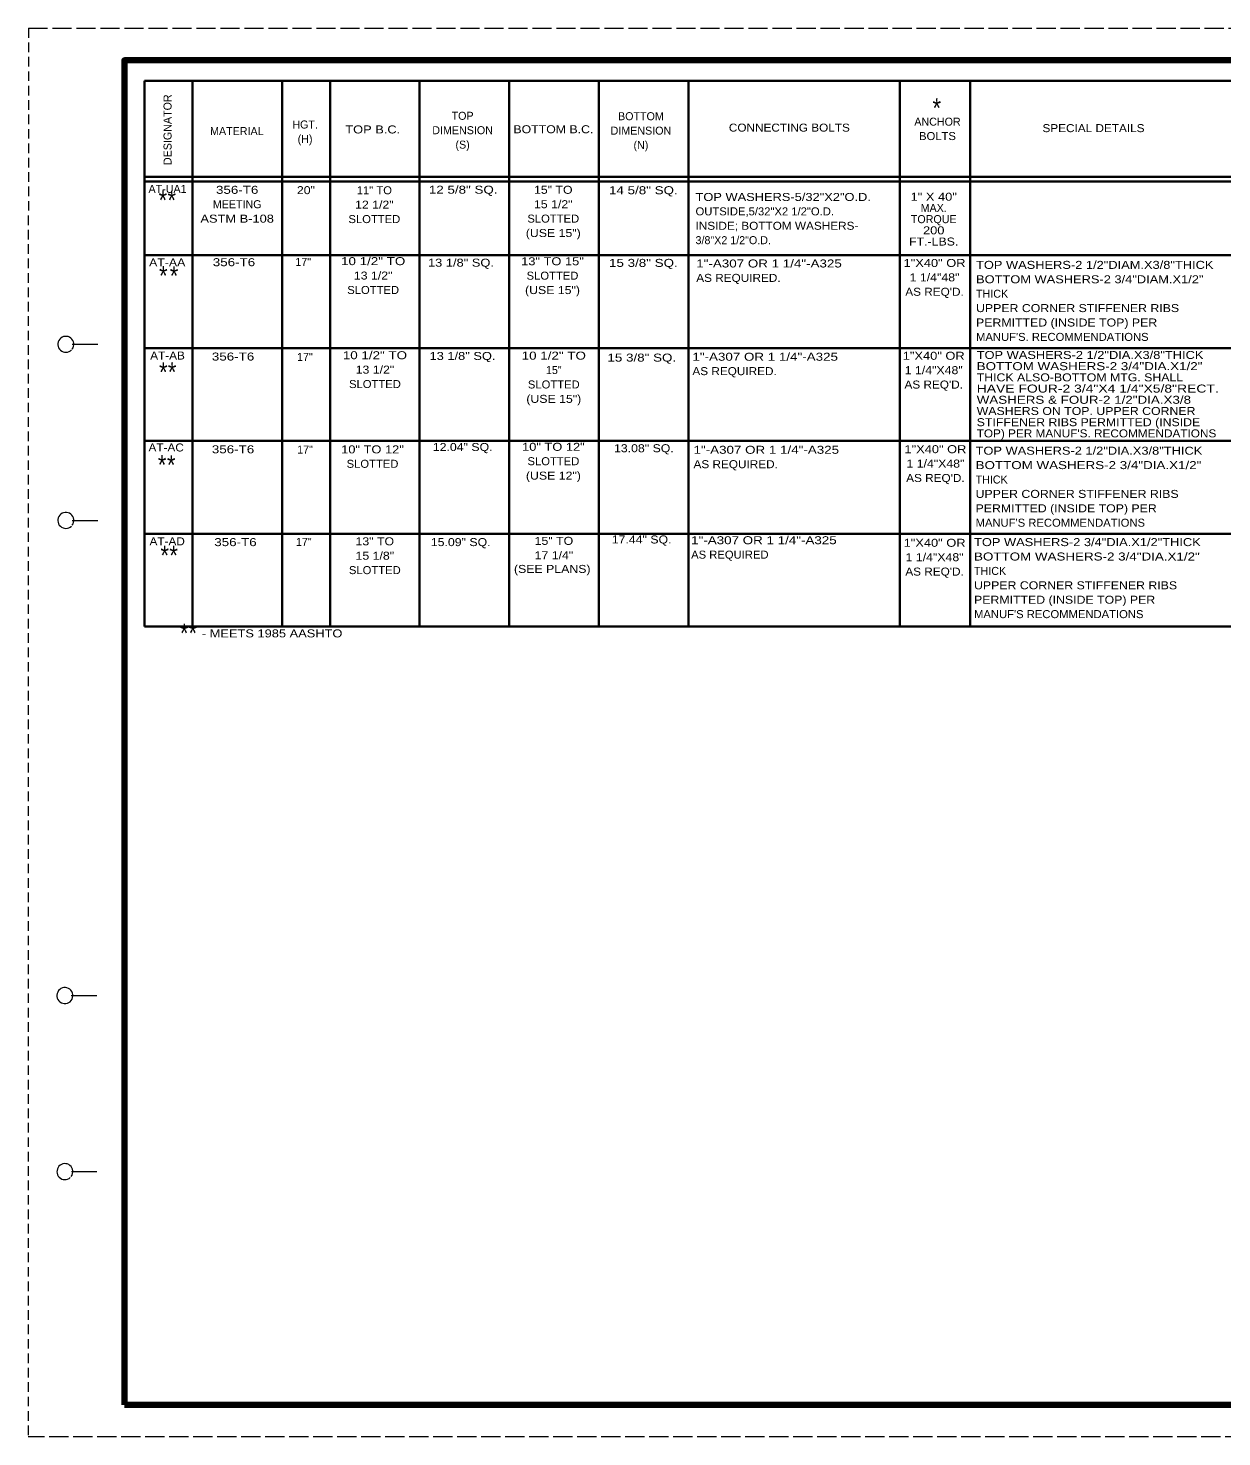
# Model space of a CAD drawing. Extents: x -993 to -313, y 154 to 594.
# Drawn here: x -993.4 to -620.4, y 154.4 to 594.4 of the extents above; entities that cross this region are included whole.
import ezdxf
from ezdxf.enums import TextEntityAlignment as Align

# ---------------------------------------------------------------- set-up
doc = ezdxf.new("R2010")
doc.units = 0
doc.linetypes.add('LONG_DASHED', pattern=[7.5, 6, -1.5])
doc.linetypes.add('MEDIUM_DASHED', pattern=[4.5, 3, -1.5])
doc.layers.add('1', color=7, linetype='Continuous', lineweight=25)
doc.layers.add('61', color=7, linetype='Continuous', lineweight=35)

msp = doc.modelspace()

# ---------------------------------------------------------------- linework, layer by layer
at = {"layer": '1', "linetype": 'MEDIUM_DASHED', "lineweight": 13}
msp.add_line((-993.343, 594.434), (-993.403, 154.394), dxfattribs=at)
at = {"layer": '1', "lineweight": 35}
for p, q in [((-957.085, 578.012), (-957.085, 407.512)), ((-520.085, 578.012), (-957.085, 578.012)), ((-942.085, 578.012), (-942.085, 407.512)), ((-914.085, 578.012), (-914.085, 407.512)), ((-899.085, 578.012), (-899.085, 407.512)), ((-871.085, 578.012), (-871.085, 407.512)), ((-843.085, 578.012), (-843.085, 407.512)), ((-815.085, 578.012), (-815.085, 407.512)), ((-787.085, 578.012), (-787.085, 407.512)), ((-721.085, 578.012), (-721.085, 407.512)), ((-699.085, 578.012), (-699.085, 407.512)), ((-520.085, 548.012), (-957.085, 548.012)), ((-520.085, 546.512), (-957.085, 546.512)), ((-520.085, 523.512), (-957.085, 523.512)), ((-520.085, 494.512), (-957.085, 494.512)), ((-520.085, 465.512), (-957.085, 465.512)), ((-520.085, 436.512), (-957.085, 436.512)), ((-520.085, 407.512), (-957.085, 407.512))]:
    msp.add_line(p, q, dxfattribs=at)
at = {"layer": '61', "linetype": 'LONG_DASHED', "lineweight": 13}
for p, q in [((-993.343, 594.434), (-313.323, 594.434)), ((-313.343, 154.414), (-993.403, 154.394))]:
    msp.add_line(p, q, dxfattribs=at)
at = {"layer": '61', "lineweight": 13}
for p, q in [((-979.623, 495.674), (-971.643, 495.694)), ((-979.643, 440.674), (-971.643, 440.674)), ((-979.923, 292.254), (-971.923, 292.254)), ((-979.903, 237.234), (-971.923, 237.234))]:
    msp.add_line(p, q, dxfattribs=at)
at = {"layer": '61', "lineweight": 158}
msp.add_line((-324.283, 164.394), (-963.343, 164.414), dxfattribs=at)
msp.add_lwpolyline([(-324.303, 584.434), (-963.343, 584.434), (-963.343, 164.414)], dxfattribs=at)
at = {"layer": '61', "lineweight": 13}
for centre, start, end in [((-981.645, 495.676), 323.13009, 316.23216), ((-981.645, 440.676), 323.13009, 315.37577), ((-981.925, 292.236), 322.67175, 321.71615), ((-981.925, 237.236), 323.13009, 312.31439)]:
    msp.add_arc(centre, 2.5, start, end, dxfattribs=at)

# ---------------------------------------------------------------- texts
at = {"layer": '1'}
msp.add_text('DESIGNATOR', height=2.5, rotation=90, dxfattribs=at).set_placement((-948.601, 551.663))
for s, height, width, p in [('*', 6, 0.85, (-710.831, 566.509)), ('*', 6, 0.85, (-952.633, 537.732)), ('*', 6, 0.85, (-949.862, 537.703)), ('TOP WASHERS-5/32"X2"O.D.', 2.5, 1.2, (-784.879, 540.456)), ('OUTSIDE,5/32"X2 1/2"O.D.', 2.5, 1.05, (-784.879, 535.956)), ('INSIDE; BOTTOM WASHERS-', 2.5, 1.1, (-784.879, 531.456)), ('*', 6, 0.85, (-952.497, 514.11)), ('*', 6, 0.85, (-949.144, 514.065)), ('1"-A307 OR 1 1/4"-A325', 2.5, 1.25, (-784.654, 519.677)), ('TOP WASHERS-2 1/2"DIAM.X3/8"THICK', 2.5, 1.2, (-697.231, 519.241)), ('AS REQUIRED.', 2.5, 1.1, (-784.654, 515.177)), ('BOTTOM WASHERS-2 3/4"DIAM.X1/2"', 2.5, 1.2, (-697.231, 514.741)), ('UPPER CORNER STIFFENER RIBS', 2.5, 1.15, (-697.231, 505.741)), ('PERMITTED (INSIDE TOP) PER', 2.5, 1.15, (-697.231, 501.241)), ("MANUF'S. RECOMMENDATIONS", 2.5, 1.05, (-697.231, 496.741)), ('AT-AB', 2.5, 1.1, (-955.271, 490.923)), ('1"-A307 OR 1 1/4"-A325', 2.5, 1.25, (-785.859, 490.544)), ('TOP WASHERS-2 1/2"DIA.X3/8"THICK', 2.5, 1.2, (-697.03, 491.101)), ('*', 6, 0.85, (-952.495, 483.998)), ('*', 6, 0.85, (-949.754, 484.021)), ('AS REQUIRED.', 2.5, 1.1, (-785.859, 486.044)), ('BOTTOM WASHERS-2 3/4"DIA.X1/2"', 2.5, 1.25, (-697.03, 487.601)), ('THICK ALSO-BOTTOM MTG. SHALL', 2.5, 1.15, (-697.03, 484.101)), ('WASHERS & FOUR-2 1/2"DIA.X3/8', 2.5, 1.25, (-697.03, 477.101)), ('HAVE FOUR-2 3/4"X4 1/4"X5/8"RECT.', 2.5, 1.3, (-697.03, 480.601)), ('WASHERS ON TOP. UPPER CORNER', 2.5, 1.15, (-697.03, 473.601)), ('STIFFENER RIBS PERMITTED (INSIDE', 2.5, 1.15, (-697.03, 470.101)), ("TOP) PER MANUF'S. RECOMMENDATIONS", 2.5, 1.1, (-697.03, 466.601)), ('1"-A307 OR 1 1/4"-A325', 2.5, 1.25, (-785.51, 461.479)), ('TOP WASHERS-2 1/2"DIA.X3/8"THICK', 2.5, 1.2, (-697.373, 461.195)), ('*', 6, 0.85, (-952.891, 455.051)), ('*', 6, 0.85, (-950.036, 455.006)), ('AS REQUIRED.', 2.5, 1.1, (-785.51, 456.979)), ('BOTTOM WASHERS-2 3/4"DIA.X1/2"', 2.5, 1.25, (-697.373, 456.695)), ('UPPER CORNER STIFFENER RIBS', 2.5, 1.15, (-697.373, 447.695)), ('PERMITTED (INSIDE TOP) PER', 2.5, 1.15, (-697.373, 443.195)), ("MANUF'S RECOMMENDATIONS", 2.5, 1.05, (-697.373, 438.695)), ('1"-A307 OR 1 1/4"-A325', 2.5, 1.25, (-786.256, 433.228)), ('*', 6, 0.85, (-952.067, 426.767)), ('*', 6, 0.85, (-949.28, 426.744)), ('AS REQUIRED', 2.5, 1.05, (-786.256, 428.728)), ('TOP WASHERS-2 3/4"DIA.X1/2"THICK', 2.5, 1.2, (-697.861, 432.641)), ('BOTTOM WASHERS-2 3/4"DIA.X1/2"', 2.5, 1.25, (-697.861, 428.141)), ('UPPER CORNER STIFFENER RIBS', 2.5, 1.15, (-697.861, 419.141)), ('PERMITTED (INSIDE TOP) PER', 2.5, 1.15, (-697.861, 414.641)), ("MANUF'S RECOMMENDATIONS", 2.5, 1.05, (-697.861, 410.141)), ('*', 6, 0.85, (-945.971, 402.457)), ('*', 6, 0.85, (-943.275, 402.479)), ('- MEETS 1985 AASHTO', 2.5, 1.2, (-939.135, 404.121))]:
    msp.add_text(s, height=height, dxfattribs=dict(at, width=width)).set_placement(p)
for s, p in [('TOP', (-857.66, 565.809)), ('BOTTOM', (-801.945, 565.682)), ('HGT.', (-906.875, 563.09)), ('DIMENSION', (-857.66, 561.309)), ('DIMENSION', (-801.945, 561.182)), ('ANCHOR', (-709.281, 563.981)), ('(H)', (-906.875, 558.59)), ('(S)', (-857.66, 556.809)), ('(N)', (-801.945, 556.682)), ('AT-UA1', (-949.856, 542.988)), ('MEETING', (-928.097, 538.185)), ('MAX.', (-710.458, 537.03)), ('TORQUE', (-710.458, 533.53)), ('17"', (-907.46, 520.187)), ('17"', (-906.938, 490.492)), ('15"', (-829.17, 486.388)), ('17"', (-906.907, 461.531)), ('17"', (-907.281, 432.712))]:
    msp.add_text(s, height=2.5, dxfattribs=at).set_placement(p, align=Align.CENTER)
for s, p in [('MATERIAL', (-936.567, 561.042)), ('3/8"X2 1/2"O.D.', (-784.879, 526.956)), ('THICK', (-697.231, 510.241)), ('THICK', (-697.373, 452.195)), ('THICK', (-697.861, 423.641))]:
    msp.add_text(s, height=2.5, dxfattribs=at).set_placement(p)
for s, width, p in [('TOP B.C.', 1.2, (-885.734, 561.55)), ('BOTTOM B.C.', 1.15, (-829.291, 561.609)), ('CONNECTING BOLTS', 1.1, (-755.569, 562.116)), ('SPECIAL DETAILS', 1.1, (-660.534, 561.957)), ('BOLTS', 1.05, (-709.281, 559.481)), ('356-T6', 1.25, (-928.097, 542.685)), ('20"', 1.15, (-906.621, 542.585)), ('11" TO', 1.05, (-885.234, 542.546)), ('12 5/8" SQ.', 1.25, (-857.477, 542.727)), ('15" TO', 1.15, (-829.331, 542.695)), ('14 5/8" SQ.', 1.25, (-801.186, 542.558)), ('1" X 40"', 1.2, (-710.458, 540.53)), ('12 1/2"', 1.15, (-885.234, 538.046)), ('15 1/2"', 1.15, (-829.331, 538.195)), ('ASTM B-108', 1.2, (-928.097, 533.685)), ('SLOTTED', 1.05, (-885.234, 533.546)), ('SLOTTED', 1.05, (-829.331, 533.695)), ('200', 1.2, (-710.458, 530.03)), ('(USE 15")', 1.15, (-829.331, 529.195)), ('FT.-LBS.', 1.15, (-710.458, 526.53)), ('AT-AA', 1.15, (-949.958, 520.021)), ('356-T6', 1.25, (-929.093, 520.077)), ('10 1/2" TO', 1.25, (-885.607, 520.404)), ('13 1/8" SQ.', 1.2, (-858.172, 519.929)), ('13" TO 15"', 1.2, (-829.573, 520.371)), ('15 3/8" SQ.', 1.25, (-801.179, 519.862)), ('1"X40" OR', 1.2, (-710.202, 519.839)), ('13 1/2"', 1.15, (-885.607, 515.904)), ('SLOTTED', 1.05, (-829.573, 515.871)), ('1 1/4"48"', 1.15, (-710.202, 515.339)), ('SLOTTED', 1.05, (-885.607, 511.404)), ('(USE 15")', 1.15, (-829.573, 511.371)), ("AS REQ'D.", 1.1, (-710.202, 510.839)), ('356-T6', 1.25, (-929.378, 490.603)), ('10 1/2" TO', 1.25, (-885.051, 491.013)), ('13 1/8" SQ.', 1.2, (-857.687, 490.788)), ('10 1/2" TO', 1.25, (-829.17, 490.888)), ('15 3/8" SQ.', 1.25, (-801.676, 490.276)), ('1"X40" OR', 1.2, (-710.46, 490.851)), ('13 1/2"', 1.15, (-885.051, 486.513)), ('1 1/4"X48"', 1.15, (-710.46, 486.351)), ('SLOTTED', 1.05, (-885.051, 482.013)), ('SLOTTED', 1.05, (-829.17, 481.888)), ("AS REQ'D.", 1.1, (-710.46, 481.851)), ('(USE 15")', 1.15, (-829.17, 477.388)), ('AT-AC', 1.1, (-950.284, 462.196)), ('356-T6', 1.25, (-929.388, 461.63)), ('10" TO 12"', 1.2, (-885.812, 461.602)), ('12.04" SQ.', 1.15, (-857.635, 462.345)), ('10" TO 12"', 1.2, (-829.29, 462.407)), ('13.08" SQ.', 1.15, (-801.019, 461.966)), ('1"X40" OR', 1.2, (-709.929, 461.669)), ('SLOTTED', 1.05, (-885.812, 457.102)), ('SLOTTED', 1.05, (-829.29, 457.907)), ('1 1/4"X48"', 1.15, (-709.929, 457.169)), ('(USE 12")', 1.15, (-829.29, 453.407)), ("AS REQ'D.", 1.1, (-709.929, 452.669)), ('17.44" SQ.', 1.15, (-801.718, 433.46)), ('AT-AD', 1.1, (-949.964, 432.886)), ('356-T6', 1.25, (-928.631, 432.632)), ('13" TO', 1.15, (-885.09, 432.89)), ('15.09" SQ.', 1.15, (-858.256, 432.641)), ('15" TO', 1.15, (-829.127, 433.028)), ('1"X40" OR', 1.2, (-710.189, 432.429)), ('15 1/8"', 1.15, (-885.09, 428.39)), ('(SEE PLANS)', 1.15, (-829.648, 424.261)), ('17 1/4"', 1.15, (-829.127, 428.528)), ('1 1/4"X48"', 1.15, (-710.189, 427.929)), ('SLOTTED', 1.05, (-885.09, 423.89)), ("AS REQ'D.", 1.1, (-710.189, 423.429))]:
    msp.add_text(s, height=2.5, dxfattribs=dict(at, width=width)).set_placement(p, align=Align.CENTER)

doc.saveas('drawing.dxf')
